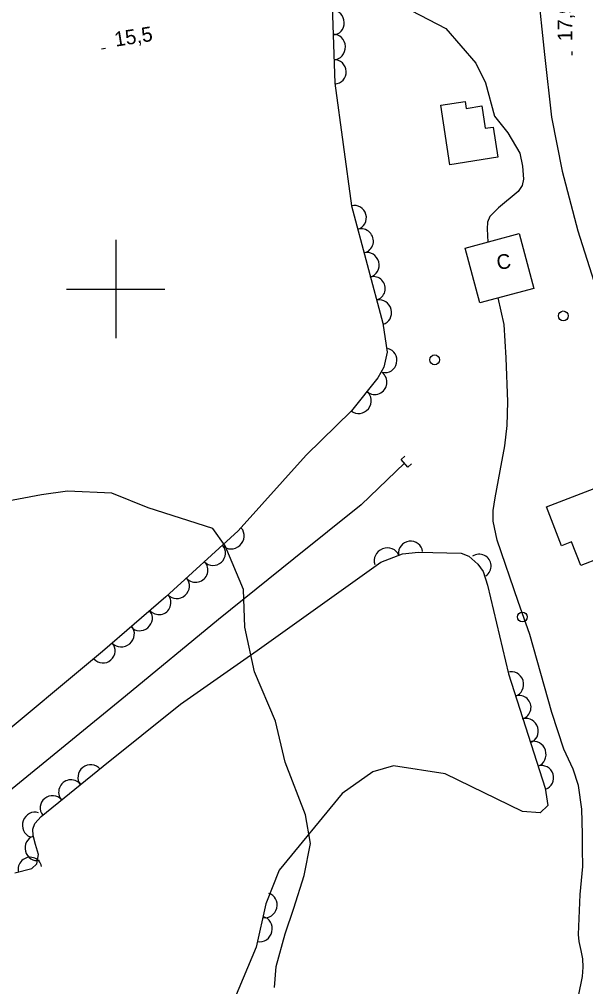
# Model space of a CAD drawing. Extents: x 646142 to 649934, y 5874075 to 5876351.
# Drawn here: x 646580.4 to 646695.7, y 5875258 to 5875454.9 of the extents above; entities that cross this region are included whole.
import ezdxf

# ---------------------------------------------------------------- set-up
doc = ezdxf.new("R2010")
doc.units = 0
for name, color, linetype in [('Niveau 2', 7, 'Continuous'), ('Niveau 21', 7, 'Continuous'), ('Niveau 26', 7, 'Continuous'), ('Niveau 3', 7, 'Continuous'), ('Niveau 31', 7, 'Continuous'), ('Niveau 36', 7, 'Continuous'), ('Niveau 4', 7, 'Continuous'), ('Niveau 44', 7, 'Continuous'), ('Niveau 61', 7, 'Continuous')]:
    doc.layers.add(name, color=color, linetype=linetype)

msp = doc.modelspace()

# ---------------------------------------------------------------- linework, layer by layer
at = {"layer": 'Niveau 2'}
for points in [[(646660.17, 5875456.66), (646667.21, 5875453.04), (646673.3, 5875445.94), (646675.26, 5875442), (646677.13, 5875435.21), (646679.83, 5875431.82), (646682.28, 5875427.65), (646682.85, 5875425)], [(646682.85, 5875425), (646683.04, 5875422.33), (646682.74, 5875421.06), (646681.93, 5875419.85), (646677.94, 5875416.56), (646676.2, 5875414.75), (646675.73, 5875413.64), (646675.61, 5875412.25), (646675.77, 5875409.52)], [(646694.21, 5875256.06), (646695.04, 5875260.05), (646695.18, 5875261.97), (646695.1, 5875263.7), (646694.77, 5875265.34), (646694.34, 5875267.23), (646694.2, 5875268.61), (646694.58, 5875276.79), (646695.08, 5875282.45), (646695.06, 5875285.97), (646695.01, 5875289.05), (646694.92, 5875294.12), (646694.2, 5875298.96), (646693.14, 5875302.3), (646691.23, 5875306.34), (646688.78, 5875313.83), (646684.33, 5875329.66), (646681.95, 5875336.42), (646677.69, 5875348.87), (646676.82, 5875352.78), (646676.86, 5875354.91), (646677.23, 5875357.53), (646678.25, 5875363), (646679.25, 5875368.08), (646679.68, 5875372.22), (646679.82, 5875377.05), (646679.48, 5875385.98), (646679.06, 5875392.77), (646677.88, 5875398.2)], [(646632.31, 5875257.83), (646632.64, 5875262.09), (646634.49, 5875268.79), (646636.29, 5875273.98), (646638.37, 5875280.65), (646639.66, 5875287.17), (646638.65, 5875293), (646634.53, 5875303.72), (646632.53, 5875312.05), (646628.25, 5875322.06), (646626.28, 5875331.21), (646625.99, 5875338.82), (646622.3, 5875347.76), (646619.8, 5875351.28), (646606.64, 5875355.49), (646599.2, 5875358.42), (646590.18, 5875358.84), (646584.91, 5875358.09), (646575.44, 5875356.36)]]:
    msp.add_lwpolyline(points, dxfattribs=at)
at = {"layer": 'Niveau 21'}
for points in [[(646685.88, 5875461.37), (646687.29, 5875447.76), (646688.74, 5875434.96), (646690.9, 5875423.99), (646694.12, 5875411.88)], [(646694.12, 5875411.88), (646697.36, 5875401.63), (646703.44, 5875384.67), (646707.64, 5875372.11), (646715.11, 5875353.03), (646720.27, 5875339.11), (646724.65, 5875326.94), (646728.22, 5875316.76), (646732.53, 5875298.96), (646733.88, 5875291.06), (646734.27, 5875285.47), (646735.5, 5875271.45), (646735.82, 5875260.33), (646735.08, 5875248.4), (646733.47, 5875241.19), (646730.1, 5875229.05), (646722.56, 5875207.8), (646716.74, 5875193.89), (646710.6, 5875181.77), (646705.33, 5875172.18), (646699.67, 5875161.96), (646695.04, 5875152.91), (646694.77, 5875152.49)]]:
    msp.add_lwpolyline(points, dxfattribs=at)
at = {"layer": 'Niveau 26'}
for p, q in [((646658.13, 5875365.28), (646658.87, 5875365.95)), ((646659.47, 5875363.77), (646658.13, 5875365.28)), ((646659.47, 5875363.77), (646660.22, 5875364.44))]:
    msp.add_line(p, q, dxfattribs=at)
at = {"layer": 'Niveau 3'}
for p, q in [((646597.12, 5875448.92), (646597.91, 5875449.04)), ((646692.94, 5875447.57), (646692.94, 5875448.37))]:
    msp.add_line(p, q, dxfattribs=at)
at = {"layer": 'Niveau 31'}
for points in [[(646668.02, 5875425.31), (646666.17, 5875437.43), (646671.12, 5875438.18), (646671.33, 5875436.78), (646674.55, 5875437.27), (646675.25, 5875432.71), (646676.87, 5875432.96), (646677.82, 5875426.81), (646668.02, 5875425.31)], [(646674.11, 5875397.19), (646671.13, 5875408.33), (646682.17, 5875411.28), (646685.15, 5875400.14), (646674.11, 5875397.19)], [(646687.7, 5875355.64), (646699.2, 5875360.08), (646701.01, 5875355.39), (646702.04, 5875355.79), (646703.31, 5875352.51), (646700.57, 5875351.45), (646702.41, 5875346.71), (646694.67, 5875343.71), (646692.81, 5875348.52), (646690.76, 5875347.72), (646687.7, 5875355.64)]]:
    msp.add_lwpolyline(points, dxfattribs=at)
at = {"layer": 'Niveau 36'}
for centre in [(646691.13, 5875394.54), (646664.93, 5875385.59), (646682.78, 5875333.26)]:
    msp.add_circle(centre, 1, dxfattribs=at)
at = {"layer": 'Niveau 4'}
msp.add_lwpolyline([(646658.8, 5875364.53), (646649.96, 5875356.08), (646636.28, 5875345.08), (646620.96, 5875332.74), (646601.97, 5875317.12), (646578.14, 5875297.69)], dxfattribs=at)
at = {"layer": 'Niveau 44'}
for points in [[(646677.67, 5875616.87), (646674.88, 5875598.79), (646670, 5875587), (646658.39, 5875553.83), (646652.67, 5875534.8), (646648.98, 5875519.15), (646646.46, 5875493.72), (646643.77, 5875465.61), (646644.62, 5875441.87), (646647.99, 5875416.95), (646654.4, 5875393.05), (646655.24, 5875387.16), (646654.57, 5875384.13), (646653.39, 5875381.94), (646648.01, 5875375.2), (646638.78, 5875366.16)], [(646638.78, 5875366.16), (646624.94, 5875350.76), (646610.19, 5875337.32), (646597.34, 5875326.22), (646573.95, 5875306.81)], [(646579.46, 5875281.17), (646582.94, 5875282.05), (646583.94, 5875283.01), (646584.25, 5875284.89), (646583.69, 5875286.91), (646583.17, 5875288.79), (646583.12, 5875290.09), (646583.51, 5875291.2), (646584.79, 5875292.64), (646597.42, 5875302.86), (646613.16, 5875315.52), (646628.78, 5875326.41), (646654.01, 5875344.42), (646658.37, 5875346.08), (646661.63, 5875346.47), (646670.32, 5875346.24), (646671.87, 5875345.61), (646673.76, 5875344.03), (646674.83, 5875342.51), (646675.68, 5875339.73), (646679.97, 5875321.68), (646687.44, 5875298.42)], [(646687.44, 5875298.42), (646687.98, 5875294.86), (646687.98, 5875294.86), (646686.39, 5875293.36), (646682.82, 5875293.66), (646667.09, 5875301.3), (646656.59, 5875302.96), (646652.33, 5875301.74), (646646.1, 5875297.32), (646633.25, 5875281.73), (646630.59, 5875274.9), (646628.63, 5875266.05), (646618.56, 5875242.09)]]:
    msp.add_lwpolyline(points, dxfattribs=at)
for centre, major_axis, ratio, start_param, end_param in [((646644.22, 5875454.22), (-0.04, 2.5), 0.919919, 3.141593, 6.283185), ((646644.35, 5875449.27), (-0.09, 2.6), 0.925819, 3.141593, 6.283185), ((646644.53, 5875444.21), (-0.09, 2.47), 0.970147, 3.141593, 6.283185), ((646648.63, 5875414.55), (-0.64, 2.39), 0.970147, 3.141593, 6.283185), ((646649.97, 5875409.76), (2.4, 0.69), 0.99999, 4.712389, 7.853982), ((646651.19, 5875404.91), (-0.64, 2.47), 0.952628, 3.141593, 6.283185), ((646652.47, 5875400.11), (2.35, 0.6), 0.997449, 4.712389, 7.853982), ((646653.85, 5875395.28), (-0.6, 2.43), 0.919919, 3.141593, 6.283185), ((646654.86, 5875385.46), (0.54, 2.41), 0.970147, 3.141593, 6.283185), ((646652.73, 5875381.04), (1.98, -1.52), 0.99999, 4.712389, 7.853982), ((646649.55, 5875377.18), (1.61, 1.98), 0.952628, 3.141593, 6.283185), ((646623.65, 5875349.6), (1.92, 1.75), 0.925819, 3.141593, 6.283185), ((646619.9, 5875346.18), (1.83, 1.67), 0.970147, 3.141593, 6.283185), ((646655.2, 5875344.86), (-2.43, -0.93), 0.925819, 3.141593, 6.283185), ((646660.03, 5875346.27), (-2.46, -0.29), 0.970147, 3.141593, 6.283185), ((646674.02, 5875343.61), (2, 1.37), 0.997449, 4.712389, 7.853982), ((646616.26, 5875342.8), (1.72, -1.81), 0.99999, 4.712389, 7.853982), ((646612.52, 5875339.49), (1.9, 1.7), 0.952628, 3.141593, 6.283185), ((646608.81, 5875336.17), (1.57, -1.86), 0.997449, 4.712389, 7.853982), ((646605.06, 5875332.83), (1.92, 1.6), 0.919919, 3.141593, 6.283185), ((646601.28, 5875329.64), (1.97, 1.7), 0.925819, 3.141593, 6.283185), ((646597.44, 5875326.32), (1.87, 1.62), 0.970147, 3.141593, 6.283185), ((646680.61, 5875319.59), (-0.76, 2.43), 0.952628, 3.141593, 6.283185), ((646682.13, 5875314.86), (2.32, 0.72), 0.997449, 4.712389, 7.853982), ((646683.73, 5875310.1), (-0.72, 2.39), 0.919919, 3.141593, 6.283185), ((646685.2, 5875305.38), (-0.79, 2.47), 0.925819, 3.141593, 6.283185), ((646594.81, 5875300.71), (-2, -1.58), 0.952628, 3.141593, 6.283185), ((646686.75, 5875300.55), (-0.76, 2.36), 0.970147, 3.141593, 6.283185), ((646590.88, 5875297.62), (-1.61, 1.91), 0.99999, 4.712389, 7.853982), ((646587.05, 5875294.46), (-1.92, -1.56), 0.970147, 3.141593, 6.283185), ((646583.44, 5875290.97), (-0.86, -2.45), 0.925819, 3.141593, 6.283185), ((646583.85, 5875286.16), (0.63, -2.42), 0.919919, 3.141593, 6.283185), ((646582.57, 5875281.92), (-0.58, 2.36), 0.997449, 4.712389, 7.853982), ((646630.56, 5875274.54), (0.59, 2.43), 0.919919, 3.141593, 6.283185), ((646629.44, 5875269.72), (0.56, 2.54), 0.925819, 3.141593, 6.283185)]:
    msp.add_ellipse(centre, major_axis=major_axis, ratio=ratio, start_param=start_param, end_param=end_param, dxfattribs=at)
at = {"layer": 'Niveau 61'}
for points in [[(646600, 5875410), (646600, 5875400), (646600, 5875390)], [(646590, 5875400), (646600, 5875400), (646610, 5875400)]]:
    msp.add_lwpolyline(points, dxfattribs=at)

# ---------------------------------------------------------------- texts
at = {"layer": 'Niveau 3'}
for s, rotation, p in [('17,9 ', 90.1276, (646692.97, 5875450.45)), ('15,5 ', 8.941, (646599.97, 5875449.32))]:
    msp.add_text(s, height=3, rotation=rotation, dxfattribs=at).set_placement(p)
at = {"layer": 'Niveau 31'}
msp.add_text('C', height=3, rotation=8.9405, dxfattribs=at).set_placement((646677.79, 5875403.88))

doc.saveas('drawing.dxf')
